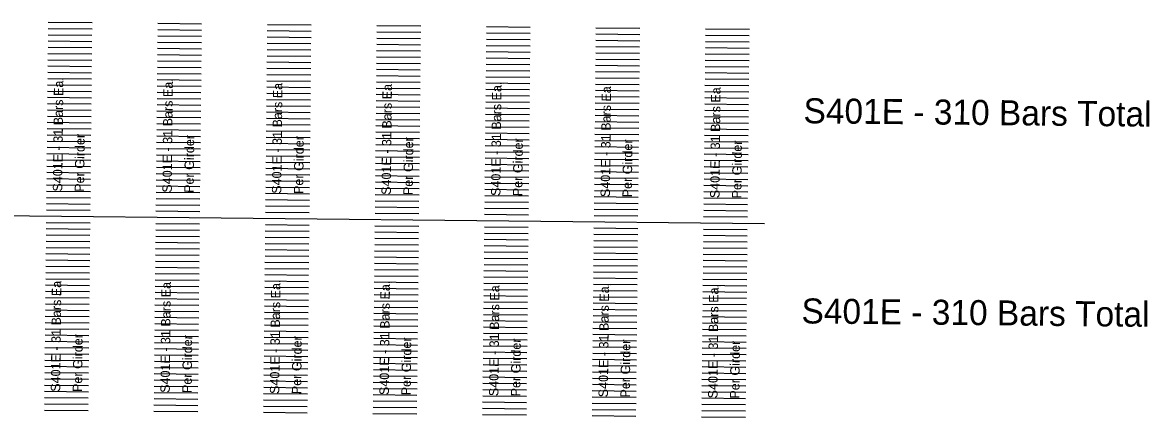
# Model space of a CAD drawing. Extents: x 632547 to 633311, y 380830 to 386139.
# Drawn here: x 633154.5 to 633244.5, y 381013.9 to 381045.5 of the extents above; entities that cross this region are included whole.
import ezdxf

# ---------------------------------------------------------------- set-up
doc = ezdxf.new("R2010")
doc.units = 0
for name, color, linetype in [('B_Border', 7, 'Continuous'), ('R_Border_Scale', 7, 'Continuous'), ('R_Wall', 7, 'Continuous')]:
    doc.layers.add(name, color=color, linetype=linetype)

msp = doc.modelspace()

# ---------------------------------------------------------------- linework, layer by layer
at = {"layer": 'B_Border'}
msp.add_line((633213.74, 381029.408), (633096.686, 381030.593), dxfattribs=at)
at = {"layer": 'R_Border_Scale'}
for p, q in [((633160.024, 381045.453), (633156.524, 381045.488)), ((633168.774, 381045.364), (633165.274, 381045.4)), ((633177.523, 381045.276), (633174.024, 381045.311)), ((633160.014, 381044.453), (633156.514, 381044.488)), ((633160.019, 381044.953), (633156.519, 381044.988)), ((633168.764, 381044.364), (633165.264, 381044.4)), ((633168.769, 381044.864), (633165.269, 381044.9)), ((633177.518, 381044.776), (633174.018, 381044.811)), ((633186.268, 381044.687), (633182.768, 381044.723)), ((633186.273, 381045.187), (633182.773, 381045.223)), ((633195.017, 381044.599), (633191.518, 381044.634)), ((633195.022, 381045.099), (633191.523, 381045.134)), ((633203.767, 381044.51), (633200.267, 381044.546)), ((633203.772, 381045.01), (633200.272, 381045.046)), ((633212.517, 381044.422), (633209.017, 381044.457)), ((633212.522, 381044.922), (633209.022, 381044.957)), ((633160.004, 381043.453), (633156.504, 381043.488)), ((633160.009, 381043.953), (633156.509, 381043.988)), ((633168.759, 381043.864), (633165.259, 381043.9)), ((633177.508, 381043.776), (633174.008, 381043.811)), ((633177.513, 381044.276), (633174.013, 381044.311)), ((633186.258, 381043.687), (633182.758, 381043.723)), ((633186.263, 381044.187), (633182.763, 381044.223)), ((633195.007, 381043.599), (633191.507, 381043.634)), ((633195.012, 381044.099), (633191.513, 381044.134)), ((633203.757, 381043.51), (633200.257, 381043.546)), ((633203.762, 381044.01), (633200.262, 381044.046)), ((633212.511, 381043.922), (633209.012, 381043.957)), ((633159.999, 381042.953), (633156.499, 381042.988)), ((633168.749, 381042.864), (633165.249, 381042.9)), ((633168.754, 381043.364), (633165.254, 381043.4)), ((633177.498, 381042.776), (633173.998, 381042.811)), ((633177.503, 381043.276), (633174.003, 381043.311)), ((633186.248, 381042.687), (633182.748, 381042.723)), ((633186.253, 381043.187), (633182.753, 381043.223)), ((633194.997, 381042.599), (633191.497, 381042.634)), ((633195.002, 381043.099), (633191.502, 381043.134)), ((633203.752, 381043.01), (633200.252, 381043.046)), ((633212.501, 381042.922), (633209.002, 381042.957)), ((633212.506, 381043.422), (633209.007, 381043.457)), ((633159.989, 381041.953), (633156.489, 381041.988)), ((633159.994, 381042.453), (633156.494, 381042.488)), ((633168.738, 381041.864), (633165.239, 381041.9)), ((633168.743, 381042.364), (633165.244, 381042.4)), ((633177.488, 381041.776), (633173.988, 381041.811)), ((633177.493, 381042.276), (633173.993, 381042.311)), ((633186.238, 381041.687), (633182.738, 381041.723)), ((633186.243, 381042.187), (633182.743, 381042.223)), ((633194.992, 381042.099), (633191.492, 381042.134)), ((633203.742, 381042.01), (633200.242, 381042.046)), ((633203.747, 381042.51), (633200.247, 381042.546)), ((633212.491, 381041.922), (633208.991, 381041.957)), ((633212.496, 381042.422), (633208.996, 381042.457)), ((633159.979, 381040.953), (633156.479, 381040.988)), ((633159.984, 381041.453), (633156.484, 381041.488)), ((633168.728, 381040.864), (633165.228, 381040.9)), ((633168.733, 381041.364), (633165.234, 381041.4)), ((633177.478, 381040.776), (633173.978, 381040.811)), ((633177.483, 381041.276), (633173.983, 381041.311)), ((633186.232, 381041.187), (633182.733, 381041.223)), ((633194.982, 381041.099), (633191.482, 381041.134)), ((633194.987, 381041.599), (633191.487, 381041.634)), ((633203.732, 381041.01), (633200.232, 381041.046)), ((633203.737, 381041.51), (633200.237, 381041.546)), ((633212.481, 381040.922), (633208.981, 381040.957)), ((633212.486, 381041.422), (633208.986, 381041.457)), ((633159.969, 381039.953), (633156.469, 381039.988)), ((633159.974, 381040.453), (633156.474, 381040.488)), ((633168.718, 381039.864), (633165.218, 381039.9)), ((633168.723, 381040.364), (633165.223, 381040.4)), ((633177.473, 381040.276), (633173.973, 381040.311)), ((633186.222, 381040.187), (633182.723, 381040.223)), ((633186.227, 381040.687), (633182.728, 381040.723)), ((633194.972, 381040.099), (633191.472, 381040.134)), ((633194.977, 381040.599), (633191.477, 381040.634)), ((633203.721, 381040.01), (633200.222, 381040.046)), ((633203.727, 381040.51), (633200.227, 381040.546)), ((633212.471, 381039.922), (633208.971, 381039.957)), ((633212.476, 381040.422), (633208.976, 381040.457)), ((633159.959, 381038.953), (633156.459, 381038.988)), ((633159.964, 381039.453), (633156.464, 381039.488)), ((633168.713, 381039.365), (633165.213, 381039.4)), ((633177.463, 381039.276), (633173.963, 381039.311)), ((633177.468, 381039.776), (633173.968, 381039.811)), ((633186.212, 381039.187), (633182.712, 381039.223)), ((633186.217, 381039.687), (633182.717, 381039.723)), ((633194.962, 381039.099), (633191.462, 381039.134)), ((633194.967, 381039.599), (633191.467, 381039.634)), ((633203.711, 381039.01), (633200.212, 381039.046)), ((633203.716, 381039.51), (633200.217, 381039.546)), ((633212.466, 381039.422), (633208.966, 381039.457)), ((633159.953, 381038.453), (633156.454, 381038.488)), ((633168.703, 381038.365), (633165.203, 381038.4)), ((633168.708, 381038.865), (633165.208, 381038.9)), ((633177.453, 381038.276), (633173.953, 381038.311)), ((633177.458, 381038.776), (633173.958, 381038.811)), ((633186.202, 381038.188), (633182.702, 381038.223)), ((633186.207, 381038.687), (633182.707, 381038.723)), ((633194.952, 381038.099), (633191.452, 381038.134)), ((633194.957, 381038.599), (633191.457, 381038.634)), ((633203.706, 381038.51), (633200.206, 381038.546)), ((633212.456, 381038.422), (633208.956, 381038.457)), ((633212.461, 381038.922), (633208.961, 381038.957)), ((633159.943, 381037.453), (633156.444, 381037.489)), ((633159.948, 381037.953), (633156.449, 381037.989)), ((633168.693, 381037.365), (633165.193, 381037.4)), ((633168.698, 381037.865), (633165.198, 381037.9)), ((633177.442, 381037.276), (633173.943, 381037.312)), ((633177.448, 381037.776), (633173.948, 381037.811)), ((633186.192, 381037.188), (633182.692, 381037.223)), ((633186.197, 381037.688), (633182.697, 381037.723)), ((633194.947, 381037.599), (633191.447, 381037.634)), ((633203.696, 381037.511), (633200.196, 381037.546)), ((633203.701, 381038.01), (633200.201, 381038.046)), ((633212.446, 381037.422), (633208.946, 381037.457)), ((633212.451, 381037.922), (633208.951, 381037.957)), ((633159.933, 381036.453), (633156.433, 381036.489)), ((633159.938, 381036.953), (633156.438, 381036.989)), ((633168.683, 381036.365), (633165.183, 381036.4)), ((633168.688, 381036.865), (633165.188, 381036.9)), ((633177.432, 381036.276), (633173.933, 381036.312)), ((633177.437, 381036.776), (633173.938, 381036.812)), ((633186.187, 381036.688), (633182.687, 381036.723)), ((633194.936, 381036.599), (633191.437, 381036.634)), ((633194.942, 381037.099), (633191.442, 381037.134)), ((633203.686, 381036.511), (633200.186, 381036.546)), ((633203.691, 381037.011), (633200.191, 381037.046)), ((633212.436, 381036.422), (633208.936, 381036.457)), ((633212.441, 381036.922), (633208.941, 381036.957)), ((633159.923, 381035.453), (633156.423, 381035.489)), ((633159.928, 381035.953), (633156.428, 381035.989)), ((633168.673, 381035.365), (633165.173, 381035.4)), ((633168.678, 381035.865), (633165.178, 381035.9)), ((633177.427, 381035.776), (633173.927, 381035.812)), ((633186.177, 381035.688), (633182.677, 381035.723)), ((633186.182, 381036.188), (633182.682, 381036.223)), ((633194.926, 381035.599), (633191.427, 381035.635)), ((633194.931, 381036.099), (633191.432, 381036.135)), ((633203.676, 381035.511), (633200.176, 381035.546)), ((633203.681, 381036.011), (633200.181, 381036.046)), ((633212.425, 381035.422), (633208.926, 381035.457)), ((633212.431, 381035.922), (633208.931, 381035.957)), ((633159.913, 381034.453), (633156.413, 381034.489)), ((633159.918, 381034.953), (633156.418, 381034.989)), ((633168.668, 381034.865), (633165.168, 381034.9)), ((633177.417, 381034.776), (633173.917, 381034.812)), ((633177.422, 381035.276), (633173.922, 381035.312)), ((633186.167, 381034.688), (633182.667, 381034.723)), ((633186.172, 381035.188), (633182.672, 381035.223)), ((633194.916, 381034.599), (633191.416, 381034.635)), ((633194.921, 381035.099), (633191.421, 381035.135)), ((633203.666, 381034.511), (633200.166, 381034.546)), ((633203.671, 381035.011), (633200.171, 381035.046)), ((633212.42, 381034.922), (633208.921, 381034.958)), ((633159.908, 381033.953), (633156.408, 381033.989)), ((633168.657, 381033.865), (633165.158, 381033.9)), ((633168.663, 381034.365), (633165.163, 381034.4)), ((633177.407, 381033.776), (633173.907, 381033.812)), ((633177.412, 381034.276), (633173.912, 381034.312)), ((633186.157, 381033.688), (633182.657, 381033.723)), ((633186.162, 381034.188), (633182.662, 381034.223)), ((633194.906, 381033.599), (633191.406, 381033.635)), ((633194.911, 381034.099), (633191.411, 381034.135)), ((633203.661, 381034.011), (633200.161, 381034.046)), ((633212.41, 381033.922), (633208.91, 381033.958)), ((633212.415, 381034.422), (633208.916, 381034.458)), ((633159.898, 381032.953), (633156.398, 381032.989)), ((633159.903, 381033.453), (633156.403, 381033.489)), ((633168.647, 381032.865), (633165.148, 381032.9)), ((633168.652, 381033.365), (633165.153, 381033.4)), ((633177.397, 381032.776), (633173.897, 381032.812)), ((633177.402, 381033.276), (633173.902, 381033.312)), ((633186.146, 381032.688), (633182.647, 381032.723)), ((633186.152, 381033.188), (633182.652, 381033.223)), ((633194.901, 381033.099), (633191.401, 381033.135)), ((633203.651, 381033.011), (633200.151, 381033.046)), ((633203.656, 381033.511), (633200.156, 381033.546)), ((633212.4, 381032.922), (633208.9, 381032.958)), ((633212.405, 381033.422), (633208.905, 381033.458)), ((633159.888, 381031.953), (633156.388, 381031.989)), ((633159.893, 381032.453), (633156.393, 381032.489)), ((633168.637, 381031.865), (633165.137, 381031.9)), ((633168.642, 381032.365), (633165.142, 381032.4)), ((633177.387, 381031.776), (633173.887, 381031.812)), ((633177.392, 381032.276), (633173.892, 381032.312)), ((633186.141, 381032.188), (633182.642, 381032.223)), ((633194.891, 381032.099), (633191.391, 381032.135)), ((633194.896, 381032.599), (633191.396, 381032.635)), ((633203.641, 381032.011), (633200.141, 381032.046)), ((633203.646, 381032.511), (633200.146, 381032.546)), ((633212.39, 381031.922), (633208.89, 381031.958)), ((633212.395, 381032.422), (633208.895, 381032.458)), ((633159.878, 381030.953), (633156.378, 381030.989)), ((633159.883, 381031.453), (633156.383, 381031.489)), ((633168.627, 381030.865), (633165.127, 381030.9)), ((633168.632, 381031.365), (633165.132, 381031.4)), ((633177.382, 381031.276), (633173.882, 381031.312)), ((633186.131, 381031.188), (633182.631, 381031.223)), ((633186.136, 381031.688), (633182.637, 381031.723)), ((633194.881, 381031.099), (633191.381, 381031.135)), ((633194.886, 381031.599), (633191.386, 381031.635)), ((633203.63, 381031.011), (633200.131, 381031.046)), ((633203.635, 381031.511), (633200.136, 381031.546)), ((633212.38, 381030.922), (633208.88, 381030.958)), ((633212.385, 381031.422), (633208.885, 381031.458)), ((633159.873, 381030.453), (633156.373, 381030.489)), ((633168.622, 381030.365), (633165.122, 381030.4)), ((633177.372, 381030.276), (633173.872, 381030.312)), ((633177.377, 381030.776), (633173.877, 381030.812)), ((633186.121, 381030.188), (633182.621, 381030.223)), ((633186.126, 381030.688), (633182.626, 381030.723)), ((633194.871, 381030.099), (633191.371, 381030.135)), ((633194.876, 381030.599), (633191.376, 381030.635)), ((633203.62, 381030.011), (633200.12, 381030.046)), ((633203.625, 381030.511), (633200.126, 381030.546)), ((633212.375, 381030.422), (633208.875, 381030.458)), ((633159.862, 381029.454), (633156.363, 381029.489)), ((633168.612, 381029.365), (633165.112, 381029.4)), ((633177.362, 381029.277), (633173.862, 381029.312)), ((633186.111, 381029.188), (633182.611, 381029.223)), ((633194.861, 381029.099), (633191.361, 381029.135)), ((633212.37, 381029.922), (633208.87, 381029.958)), ((633159.852, 381028.454), (633156.352, 381028.489)), ((633159.857, 381028.954), (633156.358, 381028.989)), ((633168.602, 381028.365), (633165.102, 381028.4)), ((633168.607, 381028.865), (633165.107, 381028.9)), ((633177.351, 381028.277), (633173.852, 381028.312)), ((633177.356, 381028.777), (633173.857, 381028.812)), ((633186.101, 381028.188), (633182.601, 381028.223)), ((633186.106, 381028.688), (633182.606, 381028.723)), ((633194.856, 381028.599), (633191.356, 381028.635)), ((633203.605, 381028.511), (633200.105, 381028.546)), ((633203.61, 381029.011), (633200.11, 381029.046)), ((633212.355, 381028.422), (633208.855, 381028.458)), ((633212.36, 381028.922), (633208.86, 381028.958)), ((633159.842, 381027.454), (633156.342, 381027.489)), ((633159.847, 381027.954), (633156.347, 381027.989)), ((633168.592, 381027.365), (633165.092, 381027.401)), ((633168.597, 381027.865), (633165.097, 381027.901)), ((633177.341, 381027.277), (633173.841, 381027.312)), ((633177.346, 381027.777), (633173.847, 381027.812)), ((633186.096, 381027.688), (633182.596, 381027.723)), ((633194.845, 381027.6), (633191.346, 381027.635)), ((633194.85, 381028.1), (633191.351, 381028.135)), ((633203.595, 381027.511), (633200.095, 381027.546)), ((633203.6, 381028.011), (633200.1, 381028.046)), ((633212.345, 381027.422), (633208.845, 381027.458)), ((633212.35, 381027.922), (633208.85, 381027.958)), ((633159.832, 381026.454), (633156.332, 381026.489)), ((633159.837, 381026.954), (633156.337, 381026.989)), ((633168.582, 381026.365), (633165.082, 381026.401)), ((633168.587, 381026.865), (633165.087, 381026.901)), ((633177.336, 381026.777), (633173.836, 381026.812)), ((633186.086, 381026.688), (633182.586, 381026.724)), ((633186.091, 381027.188), (633182.591, 381027.223)), ((633194.835, 381026.6), (633191.336, 381026.635)), ((633194.84, 381027.1), (633191.341, 381027.135)), ((633203.585, 381026.511), (633200.085, 381026.546)), ((633203.59, 381027.011), (633200.09, 381027.046)), ((633212.334, 381026.423), (633208.835, 381026.458)), ((633212.339, 381026.923), (633208.84, 381026.958)), ((633159.822, 381025.454), (633156.322, 381025.489)), ((633159.827, 381025.954), (633156.327, 381025.989)), ((633168.577, 381025.865), (633165.077, 381025.901)), ((633177.326, 381025.777), (633173.826, 381025.812)), ((633177.331, 381026.277), (633173.831, 381026.312)), ((633186.076, 381025.688), (633182.576, 381025.724)), ((633186.081, 381026.188), (633182.581, 381026.224)), ((633194.825, 381025.6), (633191.325, 381025.635)), ((633194.83, 381026.1), (633191.33, 381026.135)), ((633203.575, 381025.511), (633200.075, 381025.547)), ((633203.58, 381026.011), (633200.08, 381026.047)), ((633212.329, 381025.923), (633208.83, 381025.958)), ((633159.817, 381024.954), (633156.317, 381024.989)), ((633168.566, 381024.865), (633165.067, 381024.901)), ((633168.571, 381025.365), (633165.072, 381025.401)), ((633177.316, 381024.777), (633173.816, 381024.812)), ((633177.321, 381025.277), (633173.821, 381025.312)), ((633186.066, 381024.688), (633182.566, 381024.724)), ((633186.071, 381025.188), (633182.571, 381025.224)), ((633194.815, 381024.6), (633191.315, 381024.635)), ((633194.82, 381025.1), (633191.32, 381025.135)), ((633203.57, 381025.011), (633200.07, 381025.047)), ((633212.319, 381024.923), (633208.819, 381024.958)), ((633212.324, 381025.423), (633208.824, 381025.458)), ((633159.807, 381023.954), (633156.307, 381023.989)), ((633159.812, 381024.454), (633156.312, 381024.489)), ((633168.556, 381023.865), (633165.056, 381023.901)), ((633168.561, 381024.365), (633165.062, 381024.401)), ((633177.306, 381023.777), (633173.806, 381023.812)), ((633177.311, 381024.277), (633173.811, 381024.312)), ((633186.055, 381023.688), (633182.556, 381023.724)), ((633186.06, 381024.188), (633182.561, 381024.224)), ((633194.81, 381024.1), (633191.31, 381024.135)), ((633203.56, 381024.011), (633200.06, 381024.047)), ((633203.565, 381024.511), (633200.065, 381024.547)), ((633212.309, 381023.923), (633208.809, 381023.958)), ((633212.314, 381024.423), (633208.814, 381024.458)), ((633159.797, 381022.954), (633156.297, 381022.989)), ((633159.802, 381023.454), (633156.302, 381023.489)), ((633168.546, 381022.865), (633165.046, 381022.901)), ((633168.551, 381023.365), (633165.051, 381023.401)), ((633177.296, 381022.777), (633173.796, 381022.812)), ((633177.301, 381023.277), (633173.801, 381023.312)), ((633186.05, 381023.188), (633182.551, 381023.224)), ((633194.8, 381023.1), (633191.3, 381023.135)), ((633194.805, 381023.6), (633191.305, 381023.635)), ((633203.549, 381023.011), (633200.05, 381023.047)), ((633203.555, 381023.511), (633200.055, 381023.547)), ((633212.299, 381022.923), (633208.799, 381022.958)), ((633212.304, 381023.423), (633208.804, 381023.458)), ((633159.787, 381021.954), (633156.287, 381021.989)), ((633159.792, 381022.454), (633156.292, 381022.489)), ((633168.536, 381021.865), (633165.036, 381021.901)), ((633168.541, 381022.365), (633165.041, 381022.401)), ((633177.291, 381022.277), (633173.791, 381022.312)), ((633186.04, 381022.188), (633182.54, 381022.224)), ((633186.045, 381022.688), (633182.545, 381022.724)), ((633194.79, 381022.1), (633191.29, 381022.135)), ((633194.795, 381022.6), (633191.295, 381022.635)), ((633203.539, 381022.011), (633200.04, 381022.047)), ((633203.544, 381022.511), (633200.045, 381022.547)), ((633212.289, 381021.923), (633208.789, 381021.958)), ((633212.294, 381022.423), (633208.794, 381022.458)), ((633159.776, 381020.954), (633156.277, 381020.989)), ((633159.781, 381021.454), (633156.282, 381021.489)), ((633168.531, 381021.365), (633165.031, 381021.401)), ((633177.281, 381021.277), (633173.781, 381021.312)), ((633177.286, 381021.777), (633173.786, 381021.812)), ((633186.03, 381021.188), (633182.53, 381021.224)), ((633186.035, 381021.688), (633182.535, 381021.724)), ((633194.78, 381021.1), (633191.28, 381021.135)), ((633194.785, 381021.6), (633191.285, 381021.635)), ((633203.529, 381021.011), (633200.029, 381021.047)), ((633203.534, 381021.511), (633200.034, 381021.547)), ((633212.284, 381021.423), (633208.784, 381021.458)), ((633159.771, 381020.454), (633156.272, 381020.489)), ((633168.521, 381020.365), (633165.021, 381020.401)), ((633168.526, 381020.865), (633165.026, 381020.901)), ((633177.27, 381020.277), (633173.771, 381020.312)), ((633177.276, 381020.777), (633173.776, 381020.812)), ((633186.02, 381020.188), (633182.52, 381020.224)), ((633186.025, 381020.688), (633182.525, 381020.724)), ((633194.77, 381020.1), (633191.27, 381020.135)), ((633194.775, 381020.6), (633191.275, 381020.635)), ((633203.524, 381020.511), (633200.024, 381020.547)), ((633212.274, 381020.423), (633208.774, 381020.458)), ((633212.279, 381020.923), (633208.779, 381020.958)), ((633159.761, 381019.454), (633156.261, 381019.489)), ((633159.766, 381019.954), (633156.266, 381019.989)), ((633168.511, 381019.366), (633165.011, 381019.401)), ((633168.516, 381019.866), (633165.016, 381019.901)), ((633177.26, 381019.277), (633173.761, 381019.312)), ((633177.265, 381019.777), (633173.766, 381019.812)), ((633186.01, 381019.188), (633182.51, 381019.224)), ((633186.015, 381019.688), (633182.515, 381019.724)), ((633194.765, 381019.6), (633191.265, 381019.635)), ((633203.514, 381019.511), (633200.014, 381019.547)), ((633203.519, 381020.011), (633200.019, 381020.047)), ((633212.264, 381019.423), (633208.764, 381019.458)), ((633212.269, 381019.923), (633208.769, 381019.958)), ((633159.751, 381018.454), (633156.251, 381018.49)), ((633159.756, 381018.954), (633156.256, 381018.989)), ((633168.501, 381018.366), (633165.001, 381018.401)), ((633168.506, 381018.866), (633165.006, 381018.901)), ((633177.25, 381018.277), (633173.75, 381018.312)), ((633177.255, 381018.777), (633173.755, 381018.812)), ((633186.005, 381018.689), (633182.505, 381018.724)), ((633194.754, 381018.6), (633191.255, 381018.635)), ((633194.759, 381019.1), (633191.26, 381019.135)), ((633203.504, 381018.511), (633200.004, 381018.547)), ((633203.509, 381019.011), (633200.009, 381019.047)), ((633212.253, 381018.423), (633208.754, 381018.458)), ((633212.259, 381018.923), (633208.759, 381018.958)), ((633159.741, 381017.454), (633156.241, 381017.49)), ((633159.746, 381017.954), (633156.246, 381017.99)), ((633168.491, 381017.366), (633164.991, 381017.401)), ((633168.496, 381017.866), (633164.996, 381017.901)), ((633177.245, 381017.777), (633173.745, 381017.812)), ((633185.995, 381017.689), (633182.495, 381017.724)), ((633186, 381018.189), (633182.5, 381018.224)), ((633194.744, 381017.6), (633191.244, 381017.635)), ((633194.749, 381018.1), (633191.25, 381018.135)), ((633203.494, 381017.512), (633199.994, 381017.547)), ((633203.499, 381018.012), (633199.999, 381018.047)), ((633212.243, 381017.423), (633208.744, 381017.458)), ((633212.248, 381017.923), (633208.749, 381017.958)), ((633159.731, 381016.454), (633156.231, 381016.49)), ((633159.736, 381016.954), (633156.236, 381016.99)), ((633168.485, 381016.866), (633164.986, 381016.901)), ((633177.235, 381016.777), (633173.735, 381016.813)), ((633177.24, 381017.277), (633173.74, 381017.313)), ((633185.985, 381016.689), (633182.485, 381016.724)), ((633185.99, 381017.189), (633182.49, 381017.224)), ((633194.734, 381016.6), (633191.234, 381016.636)), ((633194.739, 381017.1), (633191.239, 381017.135)), ((633203.484, 381016.512), (633199.984, 381016.547)), ((633203.489, 381017.012), (633199.989, 381017.047)), ((633212.238, 381016.923), (633208.738, 381016.958)), ((633159.726, 381015.954), (633156.226, 381015.99)), ((633168.475, 381015.866), (633164.976, 381015.901)), ((633168.48, 381016.366), (633164.981, 381016.401)), ((633177.225, 381015.777), (633173.725, 381015.813)), ((633177.23, 381016.277), (633173.73, 381016.313)), ((633185.974, 381015.689), (633182.475, 381015.724)), ((633185.98, 381016.189), (633182.48, 381016.224)), ((633194.724, 381015.6), (633191.224, 381015.636)), ((633194.729, 381016.1), (633191.229, 381016.136)), ((633203.479, 381016.012), (633199.979, 381016.047)), ((633212.228, 381015.923), (633208.728, 381015.958)), ((633212.233, 381016.423), (633208.733, 381016.458)), ((633159.716, 381014.954), (633156.216, 381014.99)), ((633159.721, 381015.454), (633156.221, 381015.49)), ((633168.465, 381014.866), (633164.965, 381014.901)), ((633168.47, 381015.366), (633164.971, 381015.401)), ((633177.215, 381014.777), (633173.715, 381014.813)), ((633177.22, 381015.277), (633173.72, 381015.313)), ((633185.964, 381014.689), (633182.465, 381014.724)), ((633185.969, 381015.189), (633182.47, 381015.224)), ((633194.719, 381015.1), (633191.219, 381015.136)), ((633203.469, 381015.012), (633199.969, 381015.047)), ((633203.474, 381015.512), (633199.974, 381015.547)), ((633212.218, 381014.923), (633208.718, 381014.959)), ((633212.223, 381015.423), (633208.723, 381015.459)), ((633159.711, 381014.454), (633156.211, 381014.49)), ((633168.46, 381014.366), (633164.96, 381014.401)), ((633177.21, 381014.277), (633173.71, 381014.313)), ((633185.959, 381014.189), (633182.459, 381014.224)), ((633194.709, 381014.1), (633191.209, 381014.136)), ((633194.714, 381014.6), (633191.214, 381014.636)), ((633203.458, 381014.012), (633199.959, 381014.047)), ((633203.463, 381014.512), (633199.964, 381014.547)), ((633212.208, 381013.923), (633208.708, 381013.959)), ((633212.213, 381014.423), (633208.713, 381014.459))]:
    msp.add_line(p, q, dxfattribs=at)

# ---------------------------------------------------------------- texts
at = {"layer": 'R_Wall'}
for s, height, rotation, p in [('S401E - 31 Bars Ea,', 0.75, 89.43036, (633157.638, 381031.976)), ('S401E - 31 Bars Ea,', 0.75, 89.43036, (633166.387, 381031.888)), ('S401E - 31 Bars Ea,', 0.75, 89.43036, (633175.137, 381031.799)), ('S401E - 31 Bars Ea,', 0.75, 89.43036, (633183.886, 381031.711)), ('S401E - 31 Bars Ea,', 0.75, 89.43036, (633192.636, 381031.622)), ('S401E - 31 Bars Ea,', 0.75, 89.43036, (633201.386, 381031.533)), ('S401E - 31 Bars Ea,', 0.75, 89.43036, (633210.135, 381031.445)), ('S401E - 310 Bars Total', 2, 359.43036, (633216.84, 381037.442)), ('Per Girder', 0.75, 89.43036, (633159.388, 381031.959)), ('Per Girder', 0.75, 89.43036, (633168.137, 381031.87)), ('Per Girder', 0.75, 89.43036, (633176.887, 381031.782)), ('Per Girder', 0.75, 89.43036, (633185.636, 381031.693)), ('Per Girder', 0.75, 89.43036, (633194.386, 381031.605)), ('Per Girder', 0.75, 89.43036, (633203.135, 381031.516)), ('Per Girder', 0.75, 89.43036, (633211.885, 381031.428)), ('S401E - 31 Bars Ea,', 0.75, 89.43036, (633157.476, 381015.977)), ('S401E - 31 Bars Ea,', 0.75, 89.43036, (633166.225, 381015.888)), ('S401E - 31 Bars Ea,', 0.75, 89.43036, (633174.975, 381015.8)), ('S401E - 31 Bars Ea,', 0.75, 89.43036, (633183.725, 381015.711)), ('S401E - 31 Bars Ea,', 0.75, 89.43036, (633192.474, 381015.623)), ('S401E - 31 Bars Ea,', 0.75, 89.43036, (633201.224, 381015.534)), ('S401E - 31 Bars Ea,', 0.75, 89.43036, (633209.973, 381015.446)), ('S401E - 310 Bars Total', 2, 359.43036, (633216.678, 381021.442)), ('Per Girder', 0.75, 89.43036, (633159.226, 381015.96)), ('Per Girder', 0.75, 89.43036, (633167.975, 381015.871)), ('Per Girder', 0.75, 89.43036, (633176.725, 381015.782)), ('Per Girder', 0.75, 89.43036, (633185.475, 381015.694)), ('Per Girder', 0.75, 89.43036, (633194.224, 381015.605)), ('Per Girder', 0.75, 89.43036, (633202.974, 381015.517)), ('Per Girder', 0.75, 89.43036, (633211.723, 381015.428))]:
    msp.add_text(s, height=height, rotation=rotation, dxfattribs=at).set_placement(p)

doc.saveas('drawing.dxf')
